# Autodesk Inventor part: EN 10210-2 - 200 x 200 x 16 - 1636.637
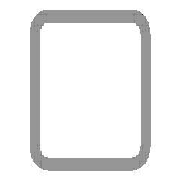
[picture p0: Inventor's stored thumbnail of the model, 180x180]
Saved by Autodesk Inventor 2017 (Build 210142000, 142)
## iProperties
IsCustomPart: 1
Created: 2017-11
Part Number: EN 10210-2 - 200 x 200 x 16 - 1636.637
Material: Steel, Mild
Description: Tube
Document SubType Name: Modeling
Standard: DIN
Designer: iusti
Standard Revision: 2006-07
Standards Organization: DIN
Language: en-US
Size Designation: 200 x 200 x 16
Categories: <MemberInstance><Categories><Category DisplayName="Structural Shapes" InternalName="089c4875-fa83-4c05-b084-43b9cc11f5ed" Mnemonic="GRDR"><CategoryParameter Dis
Stock Number: 200 x 200 x 16
Density: 7.85 g/cm^3
Appearance: Semi-Polished
Mass: 135428 g
Surface Area: 21335.1 cm^2
Volume: 17252 cm^3
_CCFamilyMember: 94
_CCFamilyDisplayName: DIN EN 10210-2 (Square) - Tube — Sizes in parentheses have been withdrawn
_FrameMemberDoc: Frame Member File
_Version: 15.0.0
_GetPNFromCC: 1
G_L: 1636.637 mm
G_W: 200.000 mm
G_H: 200.000 mm
+346FD258-9F9C-4BDE-884E-4FE9BE76FCEA+CUTDETAIL1: Miter 69.88 deg
+B95BDB02-C4C2-4ECB-9363-19BA39C44CCB+CUTDETAIL2: Miter 45.00 deg
Author: iusti
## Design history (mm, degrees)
node "Start plane"
node "End plane"
sketch "Sketch"
  geometry: L1 (-100, -76)-(-100, 76); L2 (-76, 100)-(76, 100); L3 (100, 76)-(100, -76); L4 (76, -100)-(-76, -100); L5 (-68, 84)-(68, 84); L6 (84, 68)-(84, -68); L7 (68, -84)-(-68, -84); L8 (-84, -68)-(-84, 68); L9 (0, 146.959)-(0, -146.959) reference; L10 (-146.959, 0)-(146.959, 0) reference; A1 r 24 centre (-76, -76) between (-100, -76) and (-76, -100); A2 r 24 centre (-76, 76) between (-76, 100) and (-100, 76); A3 r 24 centre (76, 76) between (100, 76) and (76, 100); A4 r 24 centre (76, -76) between (76, -100) and (100, -76); A5 r 16 centre (-68, -68) between (-84, -68) and (-68, -84); A6 r 16 centre (-68, 68) between (-68, 84) and (-84, 68); A7 r 16 centre (68, 68) between (84, 68) and (68, 84); A8 r 16 centre (68, -68) between (68, -84) and (84, -68)
  constraints: 16 end point, 16 point on circle, 16 tangent, 8 centre point, 6 equal radius, 4 parallel, 2 perpendicular, 2 other
  dimensions: "d7" = 24 radius of A1 (= G_IR); "d10" = 200 distance between parallel lines of L2 L4 (= G_H); "d11" = 200 distance between parallel lines of L1 L3 (= G_W); "d12" = 16 distance between parallel lines of L3 L6 (= G_T); "d15" = 100 distance between parallel lines of L2 L10 (= 0.5 x d10); "d16" = 100 distance between parallel lines of L9 L3 (= 0.5 x d11); "d19" = 16 radius of A5 (= G_T); "d20" = 16 distance between parallel lines of L4 L7 (= G_T)
extrude "Body" new body sketch "Sketch" stored distance "d3" = 1636.6372 (= G_L); taper "d4" = 0 deg
node "Driven Length"
  sketch "Sketch3"
    geometry: L1 (0, 0)-(10, 0) reference
    constraints: 2 end point, 1 horizontal
  workplane "Work Plane3"
  sketch "Sketch4"
    geometry: L1 (-2, -100)-(12, -100) reference; L2 (-2, 1536.637)-(12, 1536.637) reference
    dimensions: "d18" = 1636.6372 distance between parallel lines of L1 L2 (derived)
workplane "Work Plane4"
split "Split1"
workplane "Work Plane5"
split "Split2"
body "Solid1"
other parameters: "G_W" = 200 [user parameter; used in 1 equation term], "G_H" = 200 [user parameter; used in 1 equation term], "G_T" = 16 [user parameter; used in 3 equation terms], "G_IR" = 24 [user parameter; used in 1 equation term], "G_L" = 1636.6372 (= d18) [user parameter; used in 1 equation term], "G_OFFSET_END" = 36.6372 [user parameter; used in 1 equation term], "d14" = 1536.6372 (= G_OFFSET_END + B_L), "d17" = 90 deg
